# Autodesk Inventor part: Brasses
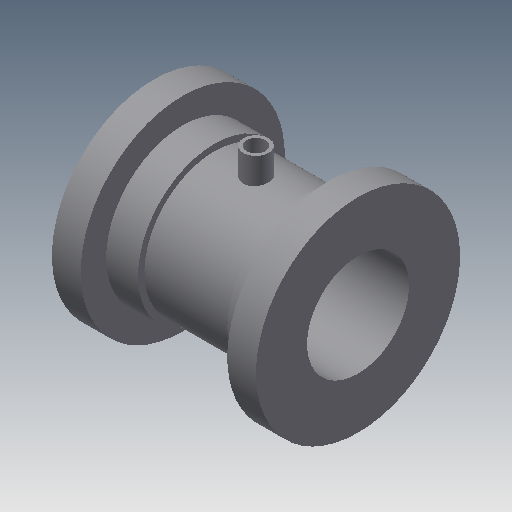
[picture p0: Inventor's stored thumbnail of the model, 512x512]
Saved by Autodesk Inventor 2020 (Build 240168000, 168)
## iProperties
Created: 2009-04
Part Number: Brasses
Document SubType Name: Modeling
Designer: Sham
Density: 1 g/cm^3
Material: Generic
Appearance: Default
Author: Sham
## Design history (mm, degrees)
sketch "Sketch1"
  geometry: L1 (0, 32)-(9, 32); L2 (0, 16)-(64, 16); L3 (64, 32)-(55, 32); L4 (55, 32)-(55, 24); L5 (55, 24)-(47, 24); L6 (19, 22)-(47, 22); L7 (47, 24)-(47, 22); L8 (19, 22)-(19, 24); L9 (19, 24)-(9, 24); L10 (9, 24)-(9, 32); L11 (0, 32)-(0, 16); L12 (64, 32)-(64, 16); L13 (-12.8, 0)-(76.8, 0) reference; 1 further point
  constraints: 24 end point, 7 parallel, 4 perpendicular, 1 collinear, 1 horizontal, 1 vertical alignment, 1 other
  dimensions: "d0" = 9 distance of L1.start L1.end; "d2" = 16 distance from line of L2 point (0, 0); "d3" = 64 distance of L2.start L2.end; "d4" = 24 distance from line of point (0, 0) L5; "d5" = 28 distance of L6.start L6.end; "d6" = 22 distance from line of point (0, 0) L6; "d7" = 8 distance of L4.end L5.end
revolve "Revolution1" sketch "Sketch1" stored, may be unused: angle "d8" = 90 deg
workplane "Work Plane1"
sketch "Sketch2"
  geometry: C1 r 4 at (-32, 0)
  constraints: 1 centre point
  dimensions: "d10" = 8 diameter of C1
extrude "Extrusion1" join sketch "Sketch2" stored distance "d11" = 10; taper "d12" = 0 deg
sketch "Sketch3"
  geometry: C1 r 4 at (0, 0) reference; C2 r 3 at (0, 0)
  constraints: 1 centre point, 1 coincident
  dimensions: "d13" = 6 diameter of C2
extrude "Extrusion2" cut sketch "Sketch3" extent not by distance; stored distance "d14" = 10; taper "d15" = 0 deg
body "Solid1"
